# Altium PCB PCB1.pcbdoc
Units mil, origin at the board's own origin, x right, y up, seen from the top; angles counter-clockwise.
Board outline 2675 x 2255.55 mil, 2 copper layers (Top Layer, Bottom Layer); 36 components, 36 nets, 173 pads, 30 vias.
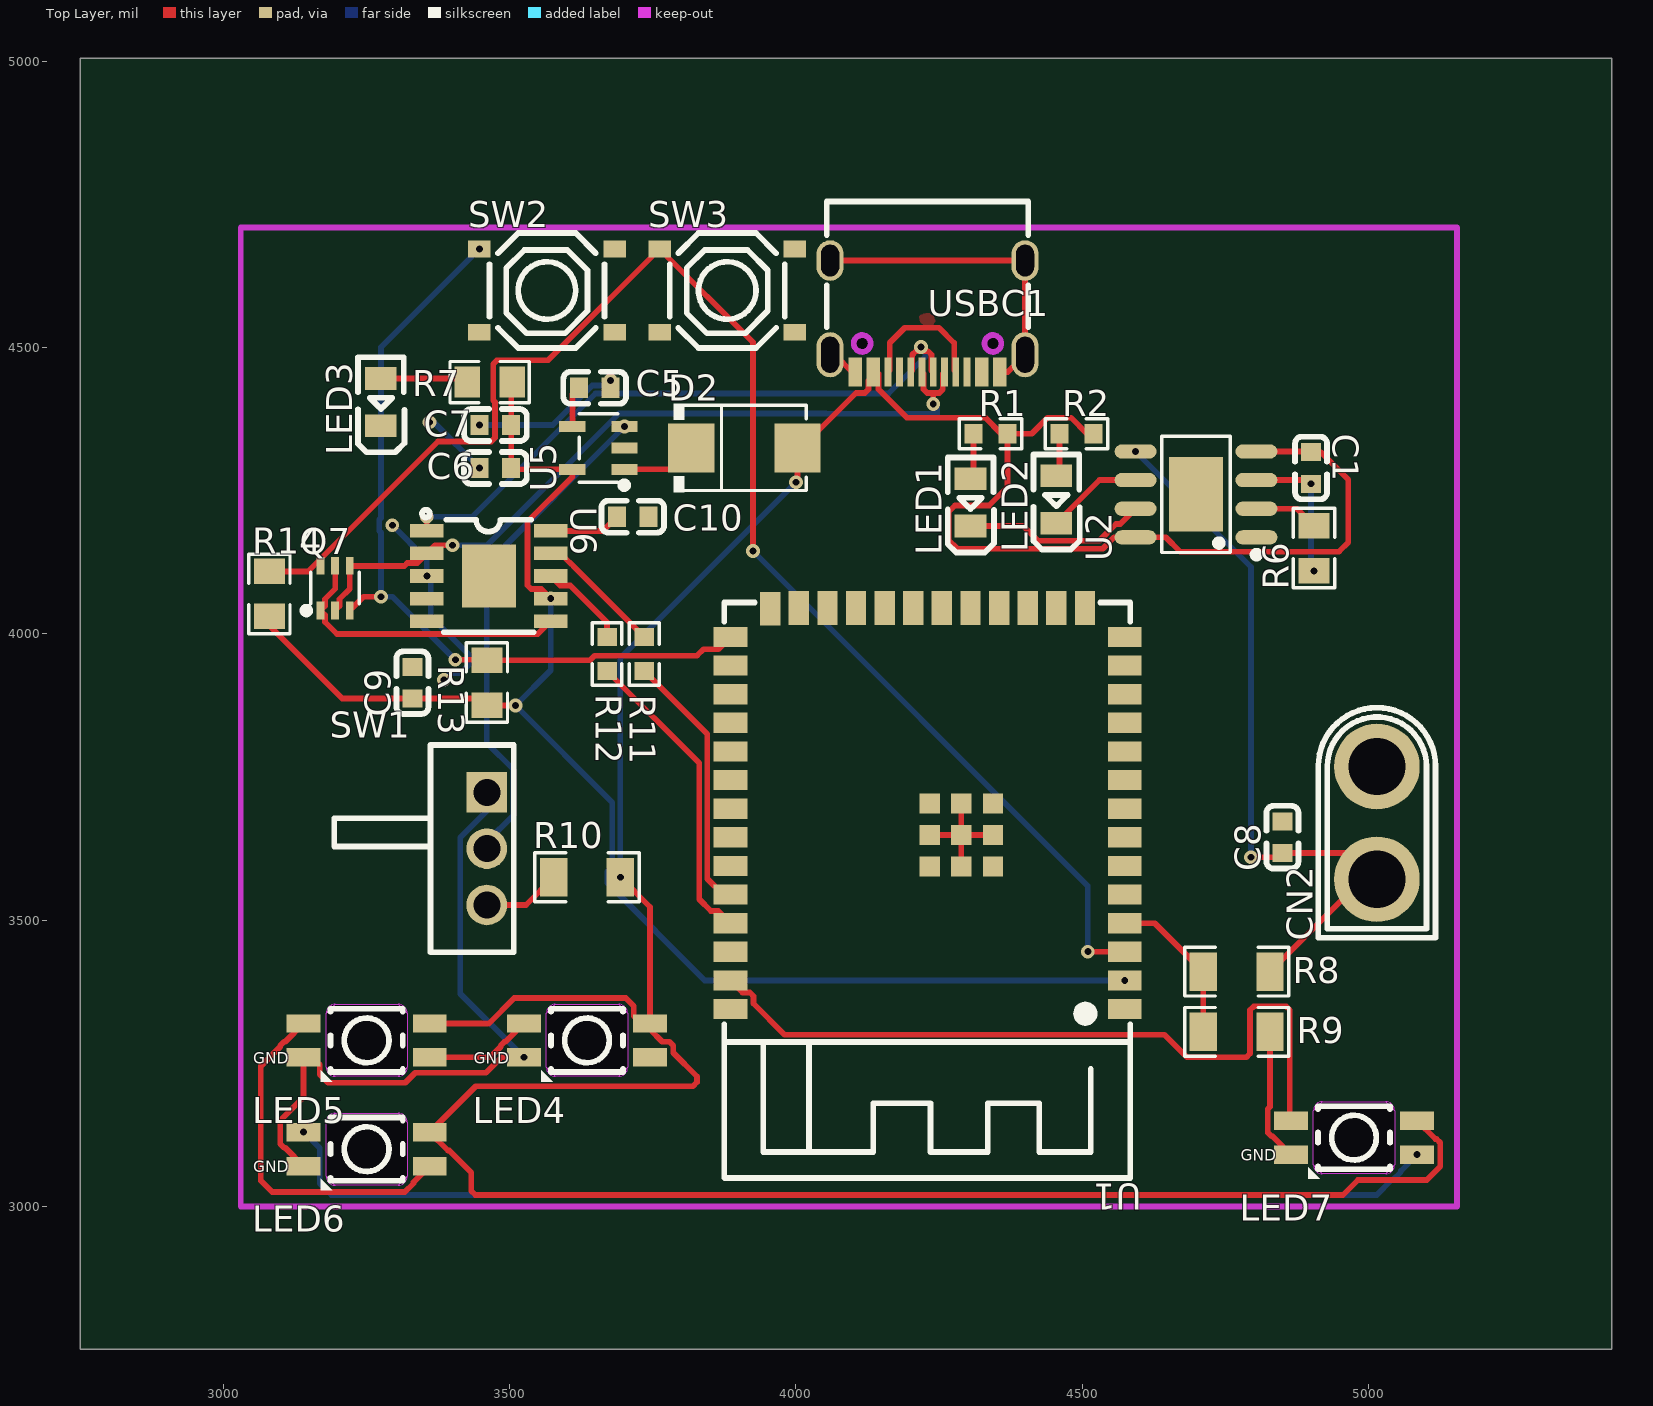
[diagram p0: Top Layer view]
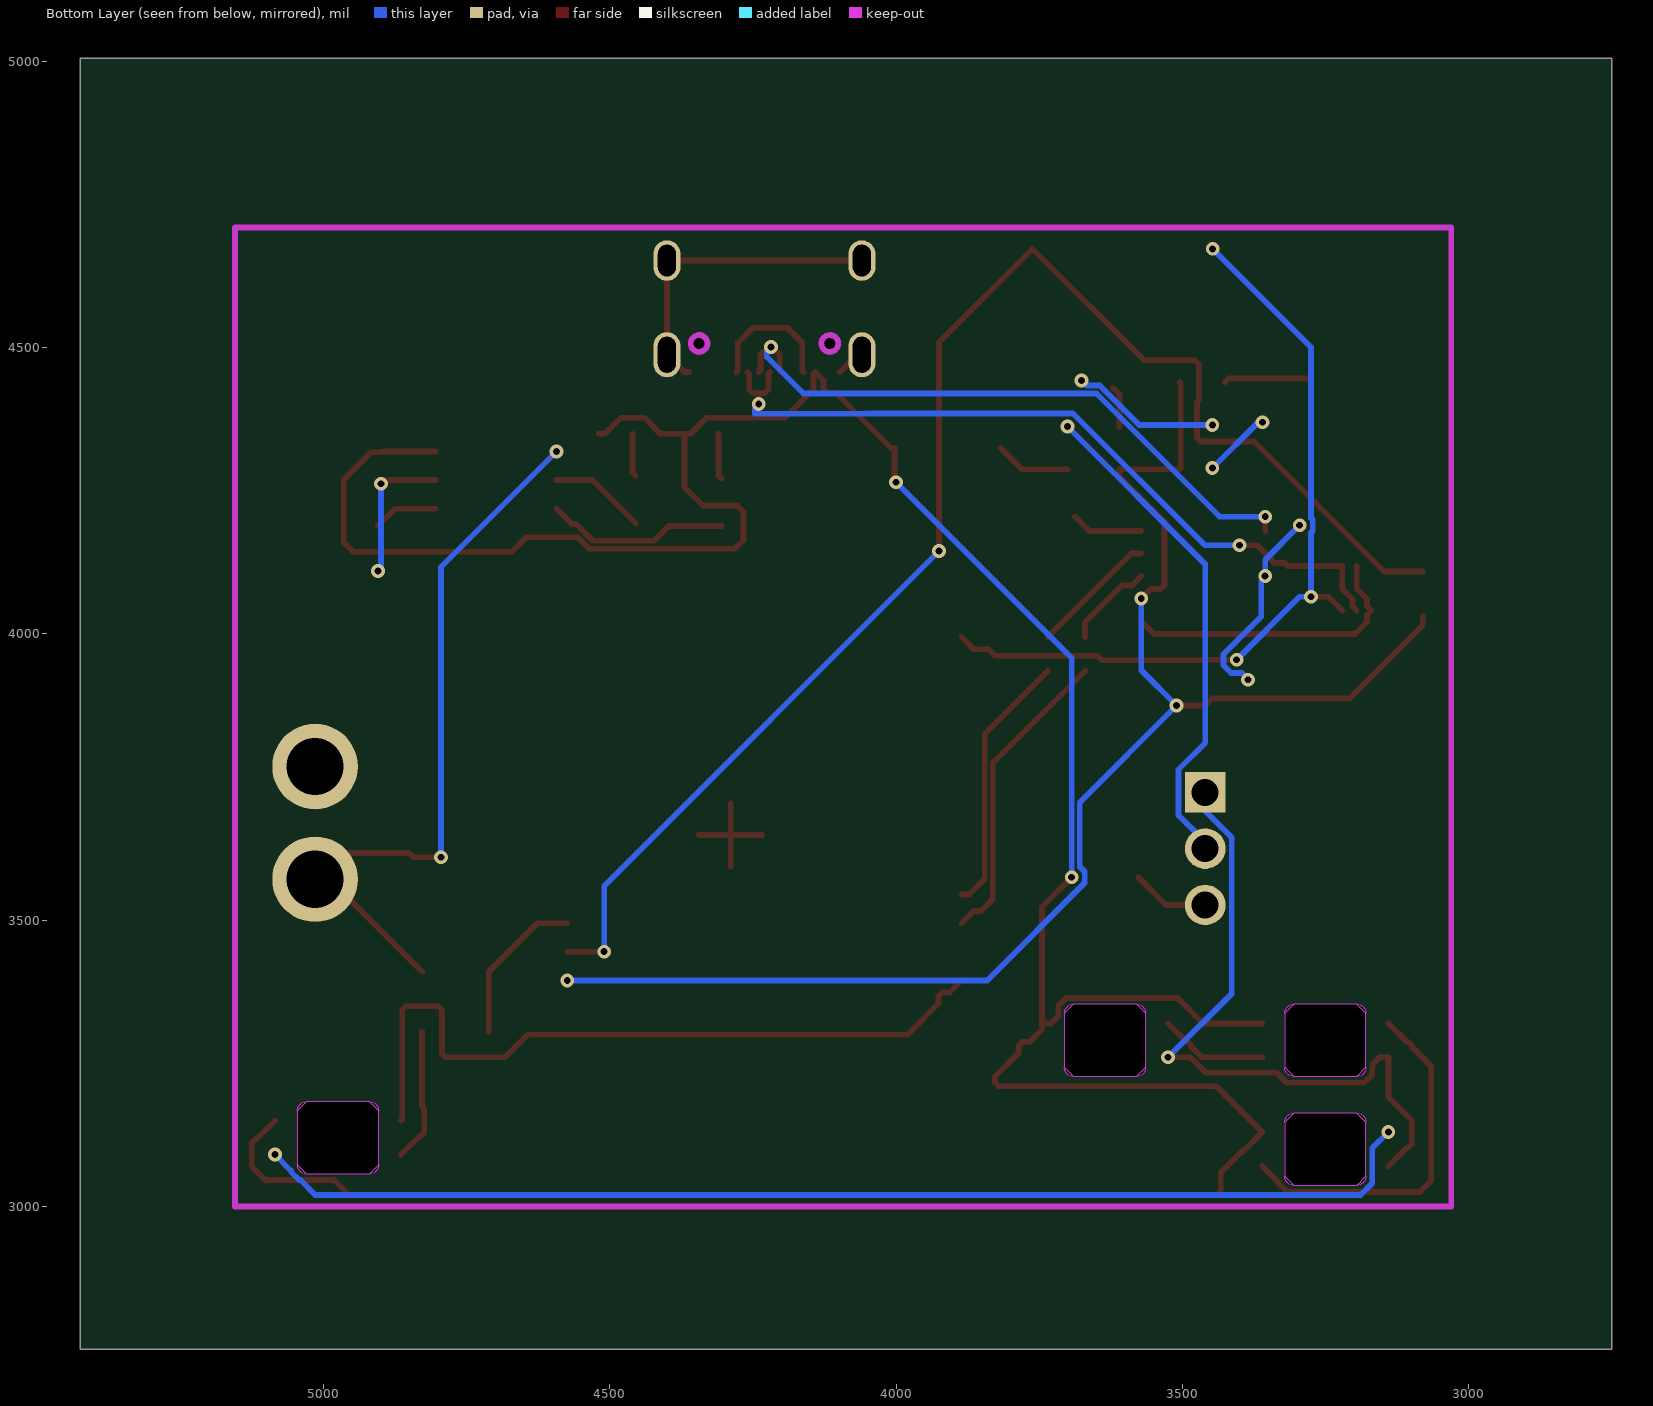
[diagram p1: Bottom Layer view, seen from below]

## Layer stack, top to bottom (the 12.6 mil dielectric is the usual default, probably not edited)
Top Layer: signal copper (thickness not stored)
Dielectric: dielectric 12.6, FR-4, Dk 4.8
Bottom Layer: signal copper (thickness not stored)

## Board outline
5425,2750 2750,2750 2750,5005.55 5425,5005.55

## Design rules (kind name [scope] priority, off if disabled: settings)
BoardOutlineClearance copperThickness1oz [All] p0: genericclearance=10 ignorepadtopadclearanceinfootprint=FALSE except(0: Arc-SplitContinuation Track-SplitContinuation SMDPad-SplitContinuation THPad-SplitContinuation Via-SplitContinuation Fill-SplitContinuation Poly-SplitContinuation Region-SplitContinuation Text-SplitContinuation; 6: Track-CutoutEdge SMDPad-CutoutEdge THPad-CutoutEdge Via-CutoutEdge Region-CutoutEdge; 11.8: Track-OutlineEdge SMDPad-OutlineEdge THPad-OutlineEdge Via-OutlineEdge Fill-OutlineEdge Region-OutlineEdge Poly-OutlineEdge Text-OutlineEdge Fill-CutoutEdge)
BoardOutlineClearance copperThickness2oz [All] p0: genericclearance=10 ignorepadtopadclearanceinfootprint=FALSE except(0: Arc-SplitContinuation Track-SplitContinuation SMDPad-SplitContinuation THPad-SplitContinuation Via-SplitContinuation Fill-SplitContinuation Poly-SplitContinuation Region-SplitContinuation Text-SplitContinuation; 6: Track-CutoutEdge SMDPad-CutoutEdge THPad-CutoutEdge Via-CutoutEdge Region-CutoutEdge; 11.8: Track-OutlineEdge SMDPad-OutlineEdge THPad-OutlineEdge Via-OutlineEdge Fill-OutlineEdge Region-OutlineEdge Poly-OutlineEdge Text-OutlineEdge Fill-CutoutEdge)
Clearance copperThickness1oz [(InNet('GND') OR InNet('+5V') OR InNet('$1N7465') OR InNet('3.3V+') OR InNet('BAT+') OR InNet('$1N9015') OR InNet('$1N7368') OR InNet('$1N1916') OR InNet('$1N2080') OR InNet('$1N1920') OR InNet('$1N2119') OR InNet('$1N7679') OR InNet('RTS') OR InNet('DN') OR InNet('IO_0') OR InNet('EN') OR InNet('$1N3425') OR InNet('BAT_VOTAGE') OR InNet('$1N8386') OR InNet('$1N9070') OR InNet('RX') OR InNet('$1N9109') OR InNet('TX') OR InNet('LDO_EN') OR InNet('MS1') OR InNet('MS2') OR InNet('MS3') OR InNet('MS4') OR InNet('B_TEMP') OR InNet('DP') OR InNet('DTR') OR InNet('CC') OR InNet('$1N13586') OR InNet('$1N13592') OR InNet('$1N13599') OR InNet('LED_DATA'))] p1: gap=7 ignorepadtopadclearanceinfootprint=FALSE except(4: Track-Track; 6: Track-SMDPad SMDPad-SMDPad Track-THPad SMDPad-THPad THPad-THPad Track-Via SMDPad-Via THPad-Via Via-Via SMDPad-Fill THPad-Fill Via-Fill Fill-Fill Track-Region SMDPad-Region THPad-Region Via-Region Region-Region Track-Poly SMDPad-Poly THPad-Poly Via-Poly Fill-Poly Region-Poly Poly-Poly Track-Text SMDPad-Text THPad-Text Via-Text Fill-Text Region-Text Poly-Text Text-Text; 6.9: Track-Hole SMDPad-Hole THPad-Hole Via-Hole Fill-Hole Region-Hole Poly-Hole Text-Hole Sheet-Hole; 11.8: Track-Fill Fill-Region Track-Sheet SMDPad-Sheet THPad-Sheet Via-Sheet Fill-Sheet Region-Sheet Poly-Sheet Text-Sheet)
Clearance copperThickness2oz [All] p1: gap=7 ignorepadtopadclearanceinfootprint=FALSE except(6: Track-SMDPad SMDPad-SMDPad Track-THPad SMDPad-THPad THPad-THPad Track-Via SMDPad-Via THPad-Via Via-Via SMDPad-Fill THPad-Fill Via-Fill Fill-Fill Track-Region SMDPad-Region THPad-Region Via-Region Region-Region Track-Poly SMDPad-Poly THPad-Poly Via-Poly Fill-Poly Region-Poly Poly-Poly Track-Text SMDPad-Text THPad-Text Via-Text Fill-Text Region-Text Poly-Text Text-Text; 6.9: Track-Hole SMDPad-Hole THPad-Hole Via-Hole Fill-Hole Region-Hole Poly-Hole Text-Hole Sheet-Hole; 8: Track-Track; 11.8: Track-Fill Fill-Region Track-Sheet SMDPad-Sheet THPad-Sheet Via-Sheet Fill-Sheet Region-Sheet Poly-Sheet Text-Sheet)
DiffPairsRouting differentialPair [All] p1: maxuncoupledlength=10 minlimit=6 maxlimit=6 mostfreqgap=6 toplayer_minwidth=5 toplayer_prefwidth=10 toplayer_maxwidth=100 bottomlayer_minwidth=5 bottomlayer_prefwidth=10 bottomlayer_maxwidth=100
PasteMaskExpansion pasteMaskExpansion [All] p1: expansion=0
PlaneConnect innerPlane [All] p1: planeconnectstyle=Relief reliefexpansion=20 reliefentries=4 reliefconductorwidth=10 reliefairgap=10
PolygonConnect copperRegion [All] p1: connectstyle=Relief reliefentries=4 reliefconductorwidth=10 polygonreliefangle="90 Angle" airgapwidth=10
RoutingVias viaSize [All] p1: viastyle="Through Hole" holewidth=12.0078 minholewidth=11.811 maxholewidth=248.0314 width=24.0158 minwidth=19.685 maxwidth=393.7008
SolderMaskExpansion solderMaskExpansion [All] p1: useseparateexpansions=TRUE expansion=2 expansionbottom=2
Width copperThickness1oz [All] p1: maxlimit=100 minlimit=5 preferedwidth=10
Width copperThickness2oz [All] p1: maxlimit=100 minlimit=8 preferedwidth=10

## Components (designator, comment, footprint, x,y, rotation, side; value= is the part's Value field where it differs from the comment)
C1 "CL10A105KB8NNNC" C0603 4900,4290 r270 top
C5 "CL10A105KB8NNNC" C0603 3648.47,4430.11 r0 top
C6 "CL10A105KB8NNNC" C0603 3475,4290 r0 top
C7 "CL10A106KP8NNNC" C0603 3475,4365 r0 top
C8 "CL10A106KP8NNNC" C0603 4850,3645 r90 top
C9 "CL10A105KB8NNNC" C0603 3330,3915 r90 top
C10 "CL10A105KB8NNNC" C0603 3715,4205 r180 top
CN2 "XT30U-M" CONN-TH_XT30U-M 5015,3670 r90 top
D2 "SS54B_C32513" SMB_L4.6-W3.6-LS5.3-RD 3910,4325 r0 top
LED1 "NCD0805R1_C84256" LED0805-R-RD 4305,4230 r90 top
LED2 "KT-0805G" LED0805-R-RD 4455,4235 r90 top
LED3 "NCD0805R1_C84256" LED0805-R-RD 3275,4405 r90 top
LED4 "SK6812MINI-E_C5149201" LED-SMD_L3.2-W2.8-LS5.9_SK6812MINI-E 3635,3290 r0 top
LED5 "SK6812MINI-E_C5149201" LED-SMD_L3.2-W2.8-LS5.9_SK6812MINI-E 3250,3290 r0 top
LED6 "SK6812MINI-E_C5149201" LED-SMD_L3.2-W2.8-LS5.9_SK6812MINI-E 3250,3100 r0 top
LED7 "SK6812MINI-E_C5149201" LED-SMD_L3.2-W2.8-LS5.9_SK6812MINI-E 4975,3120 r0 top
Q7 "2N7002DW_C699281" SOT-363_L2.0-W1.3-P0.65-LS2.1-BL 3195,4080 r0 top
R1 "RC0603JR-071KL" R0603 4340,4350 r180 top
R2 "RC0603JR-071KL" R0603 4490,4350 r180 top
R6 "0805W8F2001T5E" R0805 4905,4150 r90 top
R7 "0805W8F4700T5E" R0805 3465,4440 r180 top
R8 "1206W4F1003T5E" R1206 4770,3410 r180 top
R9 "1206W4F1003T5E" R1206 4770,3305 r0 top
R10 "1206W4F1003T5E" R1206 3635,3575 r0 top
R11 "RC0603JR-071KL" R0603 3735,3965 r90 top
R12 "RC0603JR-071KL" R0603 3670,3965 r90 top
R13 "0805W8F1002T5E" R0805 3460,3915 r90 top
R14 "0805W8F1002T5E" R0805 3080,4070 r270 top
SW1 "K3-1260D-L1" SW-TH_K3-1260D-L1 3460,3625 r0 top
SW2 "TS-1187A-B-A-B" SW-SMD_4P-L5.1-W5.1-P3.70-LS6.5-TL_H1.5 3565,4600 r0 top
SW3 "TS-1187A-B-A-B" SW-SMD_4P-L5.1-W5.1-P3.70-LS6.5-TL_H1.5 3880,4600 r0 top
U1 "ESP32-S3-WROOM-1-N8R8" WIRELM-SMD_ESP32-S3-WROOM-1 4230,3695 r180 top
U2 "TP4056_C17702041" ESOP-8_L4.9-W3.9-P1.27-LS6.0-BL-EP-1 4698.96,4243.85 r90 top
U5 "SPX3819M5-L-3-3/TR" SOT-23-5_L3.0-W1.7-P0.95-LS2.8-BL 3655,4325 r90 top
U6 "CH340K" ESOP-10_L4.9-W3.9-P1.00-LS6.2-BL-EP 3463.47,4101.33 r270 top
USBC1 "TYPE-C-31-M-12" USB-C_SMD-TYPE-C-31-M-12 4230,4555 r180 top

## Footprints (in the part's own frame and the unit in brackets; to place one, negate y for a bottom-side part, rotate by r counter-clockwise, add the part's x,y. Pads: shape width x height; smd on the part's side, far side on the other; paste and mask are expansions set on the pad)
C0603 [mm]
  rect 0.8x0.9 smd: 1(-0.7,0) 2(0.7,0)
  silkscreen extent -1.39,-0.71 1.39,0.71
CONN-TH_XT30U-M [mm]
  round 3.8 hole 2.54: 1(-2.5,0) 2(2.5,0)
  silkscreen extent -5.1,-2.6 5.11,2.6
ESOP-8_L4.9-W3.9-P1.27-LS6.0-BL-EP-1 [mm]
  oval 0.63x1.865 smd: 1(-1.905,-2.682) 2(-0.635,-2.682) 3(0.635,-2.682) 4(1.905,-2.682) 5(1.905,2.682) 6(0.635,2.682) 7(-0.635,2.682) 8(-1.905,2.682)
  rect 3.3x2.4 smd: 9(0,0)
  silkscreen extent -2.82,-2.83 2.58,1.52
ESOP-10_L4.9-W3.9-P1.00-LS6.2-BL-EP [mm]
  rect 0.6x1.5 smd: 1(-2,-2.75) 2(-1,-2.75) 3(0,-2.75) 4(1,-2.75) 5(2,-2.75) 6(2,2.75) 7(1,2.75) 8(0,2.75) 9(-1,2.75) 10(-2,2.75)
  rect 2.8x2.4 smd: 11(0,0)
  silkscreen extent -2.94,-2.96 2.5,2
LED0805-R-RD [mm]
  rect 1x1.4 smd: 1(1.05,0) 2(-1.05,0)
  silkscreen extent -2.22,-1.04 1.99,1.01
LED-SMD_L3.2-W2.8-LS5.9_SK6812MINI-E [mm]
  rect 1.5x0.82 smd: 1(2.8,0.75) 2(2.8,-0.75) 3(-2.8,-0.75) 4(-2.8,0.75)
  Board Outline Layer lines w0.005: -1.8,-1.2 -1.8,-1.2 ; -1.8,-1.2 -1.8,-1.2 ; -1.8,-1.2 ccw(c-1.4,-1.2) -1.406,-1.6 ccw(c-1.413,-1.2) -1.4,-1.6 1.4,-1.6 ; -1.8,-1.2 -1.8,-1.2 ; -1.8,-1.2 -1.8,-1.2 ; -1.8,-1.2 -1.8,1.2 cw(c-1.4,1.2) -1.4,1.6 1.4,1.6 ; 1.4,-1.6 ccw(c1.4,-1.2) 1.8,-1.2 1.8,1.2 ccw(c1.4,1.2) 1.4,1.6 ; 1.4,-1.6 1.4,-1.6 ; 1.4,1.6 1.4,1.6
  Board Outline Layer region: -1.8,-1.2 -1.8,-1.2
  Board Outline Layer region: 1.8,-1.2 1.4,-1.6 1.4,-1.6 -1.4,-1.6 -1.406,-1.6 -1.8,-1.2 -1.8,-1.2 -1.8,-1.2 -1.8,1.2 -1.4,1.6 1.4,1.6 1.4,1.6 1.8,1.2
  Multi-Layer board cut-out: -1.8,-1.2 -1.8,-1.2 -1.8,-1.2 -1.8,-1.2 -1.8,-1.2 -1.8,-1.2
  Multi-Layer board cut-out: 1.8,-1.2 1.746,-1.4 1.6,-1.547 1.4,-1.6 1.4,-1.6 1.4,-1.6 -1.4,-1.6 -1.403,-1.6 -1.406,-1.6 -1.406,-1.6 -1.604,-1.545 -1.747,-1.398 -1.8,-1.2 -1.8,-1.2 -1.8,-1.2 -1.8,-1.2 -1.8,-1.2 -1.8,-1.2 -1.8,1.2 -1.746,1.4 -1.6,1.546 -1.4,1.6 -1.4,1.6 1.4,1.6 1.4,1.6 1.6,1.547 1.746,1.4 1.8,1.2 1.8,1.2
  silkscreen extent -2.03,-1.83 1.6,1.4
R0603 [mil]
  rect 31.75x34.02 smd: 1(-29.66,0) 2(29.66,0)
  silkscreen extent -55,-26 55,26
R0805 [mm]
  rect 1.133x1.377 smd: 1(-1,0) 2(1,0)
  silkscreen extent -1.76,-0.92 1.76,0.92
R1206 [mil]
  rect 47.54x66.97 smd: 1(-58.22,0) 2(58.22,0)
  silkscreen extent -91,-42 91,42
SMB_L4.6-W3.6-LS5.3-RD [mil]
  rect 80.61x86.31 smd: 1(-92.94,0) 2(92.94,0)
  silkscreen extent -123,-77 108,77
SOT-23-5_L3.0-W1.7-P0.95-LS2.8-BL [mm]
  rect 0.49x1.157 smd: 1(-0.95,-1.154) 2(0,-1.154) 3(0.95,-1.154)
  rect 0.49x1.175 smd: 4(0.95,1.154) 5(-0.95,1.154)
  silkscreen extent -1.8,-1.29 1.53,0.85
SOT-363_L2.0-W1.3-P0.65-LS2.1-BL [mm]
  rect 0.35x0.78 smd: 1(-0.65,-0.99) 2(0,-0.99) 3(0.65,-0.99) 4(0.65,0.99) 5(0,0.99) 6(-0.65,0.99)
  silkscreen extent -1.43,-1.14 1.08,0.7
SW-SMD_4P-L5.1-W5.1-P3.70-LS6.5-TL_H1.5 [mm]
  rect 1x0.75 smd: 1(-3,1.85) 2(3,1.85) 3(-3,-1.85) 4(3,-1.85)
  silkscreen extent -2.55,-2.55 2.55,2.55
SW-TH_K3-1260D-L1 [mm]
  rect 1.8x1.8 hole 1.2: 1(0,2.5)
  round 1.8 hole 1.2: 2(0,0) 3(0,-2.5)
  silkscreen extent -6.77,-4.6 1.2,4.6
USB-C_SMD-TYPE-C-31-M-12 [mm]
  oval 1.2x2 hole 0.8 slot 1.6 at 90 deg: 0(-4.325,1.706) 1(4.325,1.706)
  oval 1.2x1.8 hole 0.8 slot 1.4 at 90 deg: 2(4.325,-2.474) 3(-4.325,-2.474)
  rect 0.3x1.3 smd: A1(-3.35,2.474) A4(-2.55,2.474) A5(-1.25,2.474) A6(-0.25,2.474) A7(0.25,2.474) A8(1.25,2.474) A9(2.55,2.474) A12(3.35,2.474) B1(3.05,2.474) B4(2.25,2.474) B5(1.75,2.474) B6(0.75,2.474) B7(-0.75,2.474) B8(-1.75,2.474) B9(-2.25,2.474) B12(-3.05,2.474)
  Board Outline Layer circle w0.005: c-2.9,1.206 r0.375
  Board Outline Layer circle w0.005: c2.9,1.206 r0.375
  Board Outline Layer circle w0.254: c-2.9,1.206 r0.375
  Board Outline Layer circle w0.254: c2.9,1.206 r0.375
  Multi-Layer board cut-out: -3.275,1.206 -3.223,1.021 -3.086,0.886 -2.9,0.837 -2.714,0.886 -2.577,1.021 -2.525,1.206 -2.525,1.206 -2.577,1.391 -2.714,1.525 -2.9,1.575 -3.086,1.525 -3.223,1.391 -3.275,1.206
  Multi-Layer board cut-out: 2.525,1.206 2.577,1.021 2.714,0.886 2.9,0.837 3.086,0.886 3.223,1.021 3.275,1.206 3.275,1.206 3.223,1.391 3.086,1.525 2.9,1.575 2.714,1.525 2.577,1.391 2.525,1.206
  silkscreen extent -4.47,-5.09 4.47,0.49
WIRELM-SMD_ESP32-S3-WROOM-1 [mm]
  rect 1.5x0.9 smd: 1(-8.75,8.895) 2(-8.75,7.625) 3(-8.75,6.355) 4(-8.75,5.085) 5(-8.75,3.815) 6(-8.75,2.545) 7(-8.75,1.275) 8(-8.75,0.005) 9(-8.75,-1.265) 10(-8.75,-2.535) 11(-8.75,-3.805) 12(-8.75,-5.075) 13(-8.75,-6.345) 14(-8.75,-7.615) 27(8.75,-7.615) 28(8.75,-6.345) 29(8.75,-5.075) 30(8.75,-3.805) 31(8.75,-2.535) 32(8.75,-1.265) 33(8.75,0.005) 34(8.75,1.275) 35(8.75,2.545) 36(8.75,3.815) 37(8.75,5.085) 38(8.75,6.355) 39(8.75,7.625) 40(8.75,8.895)
  rect 0.9x1.5 smd: 15(-6.985,-8.895) 16(-5.715,-8.895) 17(-4.445,-8.895) 18(-3.175,-8.895) 19(-1.905,-8.895) 20(-0.635,-8.895) 21(0.635,-8.895) 22(1.905,-8.895) 23(3.175,-8.895) 24(4.445,-8.895) 25(5.715,-8.895) 26(6.985,-8.865)
  rect 0.9x0.9 smd: 41(-2.9,2.575) 41(-2.9,-0.225) 41(-2.9,1.175) 41(-1.5,2.575) 41(-1.5,1.175) 41(-1.5,-0.225) 41(-0.1,2.575) 41(-0.1,1.175) 41(-0.1,-0.225)
  silkscreen extent -9,-9.14 9.02,16.39

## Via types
v1: diameter 24.02, hole 12.01, Top Layer to Bottom Layer, 30 vias

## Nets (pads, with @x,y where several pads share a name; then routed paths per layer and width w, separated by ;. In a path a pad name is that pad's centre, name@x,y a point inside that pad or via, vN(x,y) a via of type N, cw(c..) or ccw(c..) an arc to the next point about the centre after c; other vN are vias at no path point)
3.3V+: C6.2 C7.2 C9.1 R7.1 R13.1 R14.2 U1.2 U5.5 U6.7 | length 2618.3
  Top Layer w10: R14.2 3080,4015 3207.56,3887.44 C9.1 3448.19,3887.44 R13.1 3460.63,3875 v1(3510,3875) ; R7.1 3502.56,4438.19 C7.2 C6.2 3504.96,4287.6 U5.5 3609.58,4274.79 3531.22,4196.43 3531.22,4084.97 3537.66,4078.54 3555.16,4078.54 v1(3571.73,4061.96)
  Bottom Layer w10: v1(3571.73,4061.96) 3571.73,3936.73 v1(3510,3875) 3679.2,3705.8 3679.2,3593.5 3670.23,3584.52 3670.23,3565.48 3840.9,3394.8 v1(4574.49,3394.8)
$1N1916: LED1.2 U2.7 | length 322.1
  Top Layer w10: LED1.2 4397.23,4188.65 4422.9,4162.98 4530.1,4162.98 4559.36,4192.23 4566.74,4192.23 U2.7
$1N1920: LED2.2 U2.6 | length 169.5
  Top Layer w10: LED2.2 4530.2,4268.85 U2.6
$1N2080: LED1.1 R1.2 | length 80.9
  Top Layer w10: LED1.1 4310.34,4276.69 R1.2
$1N2119: LED2.1 R2.2 | length 75.9
  Top Layer w10: LED2.1 4460.34,4281.69 R2.2
$1N3425: R6.2 U2.2 | length 112.6
  Top Layer w10: U2.2 4875.52,4218.85 R6.2
$1N7368: D2.1 U5.1 | length 132.1
  Top Layer w10: U5.1 3779.66,4287.6 D2.1
$1N7465: C5.1 U5.4 | length 72.4
  Top Layer w10: U5.4 3609.58,4418.78 C5.1
$1N7679: LED3.1 R7.2 | length 153.3
  Top Layer w10: LED3.1 3419.28,4446.35 R7.2
$1N8386: R10.1 SW1.3 | length 136.8
  Top Layer w10: SW1.3 3528.35,3526.57 R10.1
$1N9015: C10.2 U6.10 | length 126
  Top Layer w10: U6.10 3662.51,4180.07 C10.2
$1N9070: R11.2 U6.9 | length 223.9
  Top Layer w10: U6.9 3588.96,4140.7 3605.53,4124.13 3605.81,4124.13 3612.25,4117.69 3612.25,4117.41 R11.2
$1N9109: R12.2 U6.8 | length 157.6
  Top Layer w10: U6.8 3588.31,4084.76 3605.81,4084.76 3670,4020.57 R12.2
$1N13586: LED4.4 LED5.2 | length 190.2
  Top Layer w10: LED5.2 3465.7,3260.47 3484.25,3279.02 3484.25,3281.16 3490.68,3287.6 3492.83,3287.6 LED4.4
$1N13592: LED5.4 LED6.2 | length 630.2
  Top Layer w10: LED5.4 3107.83,3287.6 3105.68,3287.6 3099.25,3281.16 3099.25,3279.02 3065,3244.77 3065,3045 3085,3025 3316.59,3025 3331.85,3040.26 3331.85,3042.08 LED6.2
$1N13599: LED6.4 LED7.2 | length 2057.8
  Top Layer w10: LED6.4 3139.76,3129.76 v1(3140,3130)
  Bottom Layer w10: v1(3140,3130) 3168.15,3101.85 3168.15,3052.74 3168.08,3052.67 3168.08,3040.33 3188.41,3020 5014.77,3020 5040.73,3045.96 5042.55,3045.96 5056.85,3060.26 5056.85,3062.08 v1(5085.24,3090.47)
+5V: C1.1 D2.2 LED4.1 LED5.1 LED6.1 LED7.1 R1.1 R2.1 R10.2 U2.4 U2.8 USBC1.A9 USBC1.B4 | length 6130.8
  Top Layer w10: LED5.1 3463.56,3319.53 3508.01,3363.99 3702.6,3363.99 3716.9,3349.68 3716.85,3332.58 3729.9,3319.53 LED4.1 ; v1(3693.22,3575) 3745.24,3522.98 LED4.1 ; v1(4000,4265) 4002.94,4267.94 D2.2 4008.83,4325 4104.85,4421.02 4120.38,4421.02 4126.81,4427.45 4126.81,4442.98 USBC1.B4 4144.21,4454.8 4144.21,4427.45 4193.67,4377.99 4330.77,4377.99 4358.76,4350 R1.1 ; R2.1 4508.76,4350 4480.77,4377.99 4439.91,4377.99 4411.92,4350 R1.1 ; U2.4 4898.71,4318.85 C1.1 4917.44,4317.56 4965,4270 4965,4160 4948.91,4143.91 4671.17,4143.91 4646.22,4168.85 U2.8 4555.79,4168.85 4535.91,4148.97 4281.92,4148.97 4266.47,4164.42 4266.47,4212.88 4277.9,4224.32 4337.59,4224.32 4369.66,4256.39 R1.1 ; LED7.1 5117.17,3117.6 5119.32,3117.6 5125.75,3111.16 5125.75,3069.78 5101.99,3046.02 4981.73,3046.02 4955.71,3020 3440,3020 3432.93,3027.07 3432.93,3058.98 3394.32,3097.6 3392.17,3097.6 LED6.1 3440.71,3210 3820,3210 3827.07,3217.07 3827.07,3227.07 3785.75,3268.39 3785.75,3281.16 3779.32,3287.6 3766.55,3287.6 3745.24,3308.9 LED4.1
  Bottom Layer w10: v1(3693.22,3575) 3693.22,3958.22 v1(4000,4265)
B_TEMP: U2.1
BAT+: C8.1 CN2.1 R8.1 U2.5 | length 1288.2
  Top Layer w10: v1(4795,3610) 4842.56,3610 C8.1 4969.14,3617.44 CN2.1 4989.8,3571.57 R8.1
  Bottom Layer w10: v1(4593.35,4318.85) 4795,4117.2 v1(4795,3610)
BAT_VOTAGE: R8.2 R9.1 U1.4 | length 277.4
  Top Layer w10: U1.4 4626.98,3494.8 R8.2 R9.1
CC: USBC1.A5 USBC1.B5 | length 238.9
  Top Layer w10: USBC1.B5 4163.91,4460.4 4163.91,4508.91 4190,4535 4250,4535 4276.42,4508.58 4276.42,4460.38 USBC1.A5
DN: Q7.2 Q7.4 U6.2 USBC1.A7 USBC1.B7 | length 1366.5
  Top Layer w10: Q7.2 3202.72,4048.74 3202.72,4060.93 3220.59,4078.8 Q7.4 3315.97,4118.98 3321.13,4124.13 3338.63,4124.13 U6.2 3369.5,4155 v1(3400,4155) ; USBC1.A7 4222.95,4454.8 4222.95,4427.45 4229.38,4421.02 4239.56,4421.02 ; v1(4240,4402.01) 4240,4420.58 4239.56,4421.02 ; USBC1.B7 4256.73,4454.79 4256.73,4427.45 4250.3,4421.02 4239.56,4421.02
  Bottom Layer w10: v1(3400,4155) 3460.5,4155 3690.9,4385.39 4052.73,4385.39 4053.18,4384.94 4247.07,4384.94 4247.07,4394.94 v1(4240,4402.01)
DP: U6.1 USBC1.A6 USBC1.B6 | length 1133.1
  Top Layer w10: v1(3355,4205) 3355,4180.28 U6.1 ; USBC1.B6 4203.27,4460.39 4203.27,4487.73 4209.7,4494.17 4230.62,4494.17 4237.05,4487.73 4237.05,4460.38 USBC1.A6
  Bottom Layer w10: v1(3355,4205) 3435,4205 3650,4420 4161.64,4420 4225.74,4484.1 4225.74,4494.1 v1(4218.67,4501.18)
DTR: U6.4
EN: Q7.6 R14.1 SW3.1 U1.3 | length 2597.4
  Top Layer w10: R14.1 3147.62,4109.37 3374.54,4336.3 3467.74,4336.3 3474.17,4342.73 3474.17,4405.26 3471.09,4408.34 3471.09,4471.66 3477.53,4478.09 3567.15,4478.09 SW3.1 3925,4509.72 v1(3925,4145) ; v1(4510,3445) 4510.19,3444.8 U1.3
  Bottom Layer w10: v1(3925,4145) 4510,3560 v1(4510,3445)
GND: C1.2 C5.2 C6.1 C7.1 C8.2 C9.2 C10.1 CN2.2 LED3.2 LED4.3 LED5.3 LED6.3 LED7.3 R6.1 R9.2 SW1.1 SW2.4 SW3.4 U1.1 U1.40 U1.41 U2.3 U5.2 U6.3 USBC1.0 USBC1.1 USBC1.2 USBC1.3 USBC1.A1 USBC1.A12 USBC1.B1 USBC1.B12 | length 3235.4
  Top Layer w10: LED6.3 3107.83,3102.4 3105.68,3102.4 3099.25,3108.84 3099.25,3150.22 3139.76,3190.73 LED5.3 3155.1,3260.47 3168.15,3247.42 3168.15,3242.74 3168.08,3242.67 3168.08,3230.33 3182.39,3216.02 3317.61,3216.02 3334.94,3233.34 3458.4,3233.34 3485.52,3260.47 v1(3524.76,3260.47) ; USBC1.1 4067.86,4487.84 USBC1.A12 ; USBC1.2 USBC1.3 USBC1.0 4370.03,4457.59 USBC1.A1 ; U1.41@4233.94,3648.74 U1.41@4289.06,3648.74 ; U1.41@4289.06,3593.62 U1.41@4289.06,3648.74 ; U1.41@4289.06,3703.86 U1.41@4289.06,3648.74 ; U1.41@4344.18,3648.74 U1.41@4289.06,3648.74 ; U2.3 4893.59,4268.85 v1(4900,4262.44) ; R9.2 4828.22,3174.19 4824.25,3170.22 4824.25,3128.84 4830.68,3122.4 4832.83,3122.4 LED7.3 ; v1(4905,4110) R6.1
  Bottom Layer w10: v1(3295,4190) 3355.2,4129.8 v1(3355.2,4101.33) 3362.28,4094.26 3362.28,4030.24 3427.99,3964.52 3427.99,3945.48 3414.52,3932.01 3395.48,3932.01 3385,3921.53 v1(3385,3920) ; v1(3360,4370) 3367.44,4370 v1(3447.44,4290) ; v1(3447.44,4365) 3575.18,4365 3644.19,4434.02 3667.05,4434.02 v1(3676.03,4442.99) ; SW1.1 3460,3690.64 3413.58,3644.23 3413.58,3371.65 v1(3524.76,3260.47) ; v1(4900,4262.44) 4900,4115 v1(4905,4110)
IO_0: Q7.3 R13.2 SW2.1 U1.27 | length 1418.9
  Top Layer w10: Q7.3 3244.57,4065 v1(3275,4065) ; v1(3405,3955) 3459.37,3955 R13.2 3640.61,3954.37 3648.44,3962.2 3827.26,3962.2 3838.56,3973.51 3864.21,3973.51 U1.27
  Bottom Layer w10: v1(3405,3955) 3295,4065 v1(3275,4065) 3275,4177.48 3272.01,4180.48 3272.01,4199.52 3275,4202.52 3275,4500.94 v1(3446.89,4672.83)
  other v1: 3275,4065
LDO_EN: SW1.2 U5.3 | length 875.4
  Bottom Layer w10: SW1.2 3460,3637.02 3506.42,3683.44 3506.42,3763.4 3460,3809.82 3460,4121.98 v1(3700.42,4362.4)
LED_DATA: LED7.4 U1.39 | length 1318.9
  Top Layer w10: U1.39 3906.81,3373.51 3919.59,3373.51 3926.02,3367.07 3926.02,3354.29 3980.32,3300 4643.99,3300 4683.46,3260.53 4787.03,3260.53 4793.47,3266.97 4793.47,3343.03 4799.9,3349.47 4856.54,3349.47 4862.97,3343.03 4862.97,3151.32 LED7.4
MS1: U1.6
MS2: U1.7
MS3: U1.8
MS4: U1.9
RTS: Q7.1 Q7.5 U6.6 | length 524.5
  Top Layer w10: Q7.5 3195,4078.8 3177.13,4060.93 3177.13,4048.74 Q7.1 3177.13,4033.31 3177.13,4021.12 3198.45,3999.8 3548.94,3999.8 U6.6
RX: R11.1 U1.36 | length 460.4
  Top Layer w10: R11.1 3845,3825.34 3845,3572.54 3872.73,3544.8 U1.36
TX: R12.1 U1.37 | length 537.3
  Top Layer w10: R12.1 3830.98,3774.36 3830.98,3536.55 3851.43,3516.1 3864.21,3516.1 U1.37
pads on no net: LED4.2 SW2.2 SW2.3 SW3.2 SW3.3 U1.5 U1.10 U1.11 U1.12 U1.13 U1.14 U1.15 U1.16 U1.17 U1.18 U1.19 U1.20 U1.21 U1.22 U1.23 U1.24 U1.25 U1.26 U1.28 U1.29 U1.30 U1.31 U1.32 U1.33 U1.34 U1.35 U1.38 U2.9 U6.5 U6.11 USBC1.A4 USBC1.A8 USBC1.B8 USBC1.B9

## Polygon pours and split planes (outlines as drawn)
GND on Top Layer (solid, remove dead copper, pour order 0): 3000,4670 5175,4670 5175,3305 3000,3305

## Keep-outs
Board Outline Layer:
  lines w10: 3030,3000 5155,3000 5155,4710 3030,4710 3030,3000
